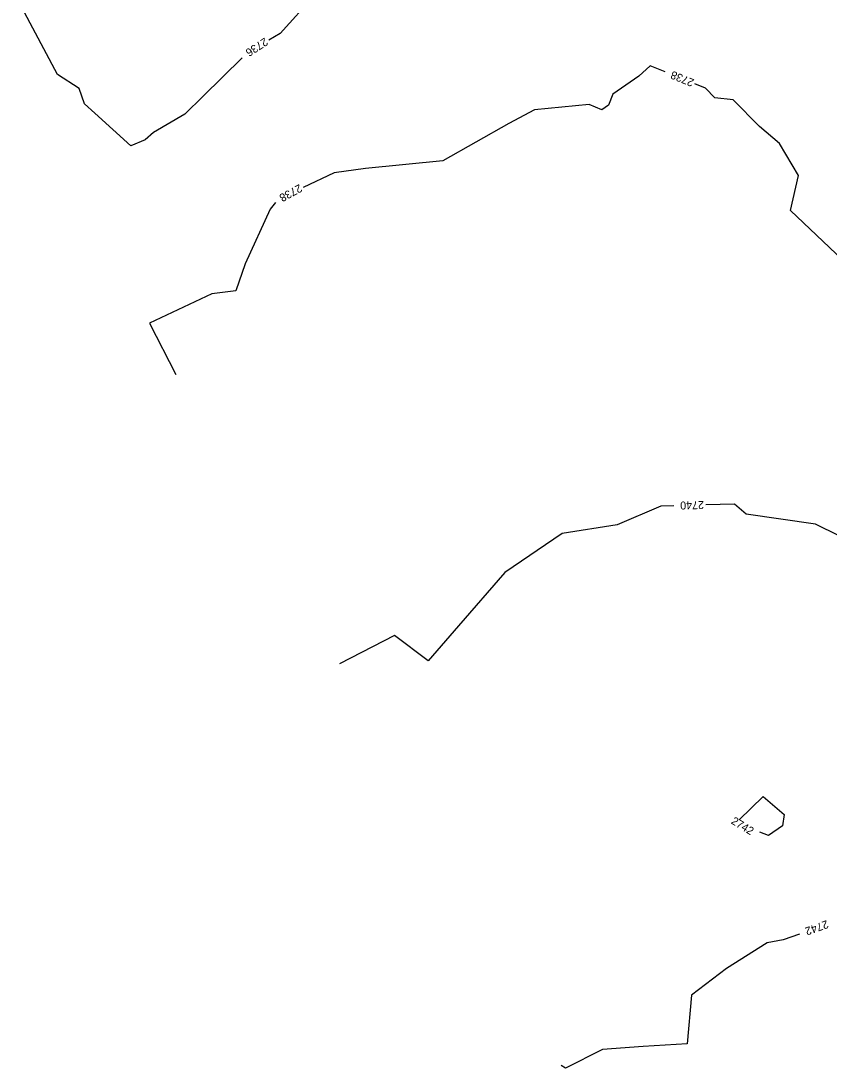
# Model space of a CAD drawing. Extents: x 1326424 to 1329294, y 1001359 to 1003823.
# Drawn here: x 1327761.9 to 1327963.8, y 1001871.3 to 1002132.9 of the extents above; entities that cross this region are included whole.
import ezdxf

# ---------------------------------------------------------------- set-up
doc = ezdxf.new("R2010")
doc.units = 0
doc.layers.add('Prop Rem of Exist Asph Pvmt', color=7, linetype='Continuous')
doc.layers.add('Scratch_Level_3', color=7, linetype='Continuous')

msp = doc.modelspace()

# ---------------------------------------------------------------- linework, layer by layer
at = {"layer": 'Prop Rem of Exist Asph Pvmt'}
for points in [[(1328025.79, 1001979.07), (1328016.11, 1001981.49), (1328009.07, 1001983.82), (1327992.62, 1001990.33), (1327991.34, 1001990.74), (1327990.09, 1001991.57), (1327966.28, 1002004.24), (1327960.37, 1002007.16), (1327943.04, 1002009.7), (1327940.17, 1002012.18), (1327932.97, 1002011.99)], [(1327924.97, 1002011.79), (1327921.76, 1002011.7), (1327910.83, 1002007.05), (1327897.07, 1002004.83), (1327882.81, 1001995.13), (1327871.24, 1001981.77), (1327863.64, 1001973), (1327855.19, 1001979.35), (1327841.46, 1001972.3)]]:
    msp.add_lwpolyline(points, dxfattribs=at)
at = {"layer": 'Scratch_Level_3'}
for points in [[(1327903.96, 1002180.88), (1327901.64, 1002180.74), (1327897.52, 1002178.77), (1327890.6, 1002178.73), (1327878.56, 1002176.93), (1327866.6, 1002166.18), (1327865.81, 1002164.88), (1327861.26, 1002162.72), (1327854.02, 1002157.6), (1327848.97, 1002154.32), (1327839.53, 1002143.49), (1327835.25, 1002139.4), (1327826.64, 1002129.83), (1327823.78, 1002128.12)], [(1327817.11, 1002123.75), (1327807.38, 1002114.15), (1327802.8, 1002109.65), (1327795.02, 1002105.08), (1327792.9, 1002103.21), (1327789.3, 1002101.71), (1327780.32, 1002109.9), (1327777.72, 1002112.26), (1327776.42, 1002116.1), (1327771.01, 1002119.59), (1327762.05, 1002136.31), (1327761.87, 1002137.68), (1327762.47, 1002142.9), (1327764.97, 1002155.04)], [(1327922.85, 1002120.19), (1327919.07, 1002121.72), (1327916.27, 1002119.11), (1327909.8, 1002114.65), (1327908.66, 1002111.93), (1327907.04, 1002110.72), (1327903.88, 1002112.03), (1327890.15, 1002110.7), (1327883.81, 1002107.33), (1327867.27, 1002097.95), (1327847.98, 1002096.09), (1327840.1, 1002095.02), (1327832.41, 1002091.36)], [(1327988.44, 1002042.98), (1327981.21, 1002055.2), (1327974.15, 1002065.32), (1327967.11, 1002073.28), (1327954.15, 1002085.58), (1327956.15, 1002094.31), (1327951.43, 1002102.33), (1327946.39, 1002106.53), (1327939.87, 1002113.2), (1327935.29, 1002113.74), (1327932.9, 1002116.12), (1327930.27, 1002117.19)], [(1327825.47, 1002087.56), (1327824.14, 1002085.92), (1327817.9, 1002072.23), (1327815.56, 1002065.48), (1327809.57, 1002064.76), (1327794.02, 1002057.41), (1327800.58, 1002044.57)], [(1327941.33, 1001933.32), (1327947.33, 1001939.15)], [(1327947.33, 1001939.15), (1327952.58, 1001934.64), (1327952.19, 1001931.78), (1327948.69, 1001929.41), (1327946.49, 1001930.17)], [(1327956.41, 1001904.76), (1327952.36, 1001903.32), (1327948.29, 1001902.53), (1327938.14, 1001896.13), (1327929.38, 1001889.44), (1327928.36, 1001877.3), (1327917.31, 1001876.61), (1327907.19, 1001875.88), (1327897.97, 1001871.26), (1327896.82, 1001871.93)]]:
    msp.add_lwpolyline(points, dxfattribs=at)

# ---------------------------------------------------------------- texts
at = {"layer": 'Prop Rem of Exist Asph Pvmt'}
msp.add_text('2740', height=2, rotation=181.4881, dxfattribs=at).set_placement((1327932.52, 1002012.98))
at = {"layer": 'Scratch_Level_3'}
for s, rotation, p in [('2736', 213.2374, (1327822.77, 1002128.85)), ('2738', 157.9472, (1327930.23, 1002118.28)), ('2738', 208.7226, (1327831.43, 1002092.23)), ('2742', 328.5904, (1327939.13, 1001932.49)), ('2742', 199.6267, (1327963.21, 1001908.25))]:
    msp.add_text(s, height=2, rotation=rotation, dxfattribs=at).set_placement(p)

doc.saveas('drawing.dxf')
